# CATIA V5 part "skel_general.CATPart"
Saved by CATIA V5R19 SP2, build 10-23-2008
Part number: skel_general
Bounding box of the stored display mesh (mm): x -7 to 8, y 0 to 31.173, z 0 to 17.806
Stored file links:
  E:\TRAVAIL\IAO\skel_general.CATPart
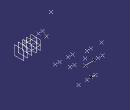
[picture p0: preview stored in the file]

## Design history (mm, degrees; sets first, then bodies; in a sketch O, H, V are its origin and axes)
Parameters
  LongueurBC = 10 mm
  LongueurBM = 10 mm
  LongueurAE = 5.4 mm
  LongueurCE = 13 mm
  LongueurDM = 16.03 mm
  LongueurDF = 6.95 mm
  LongueurCF = 18 mm
  LongueurEF = 27.8 mm
  beta = 80 deg
  LongueurAB = 10 mm
  ep = 2 mm
  Longueur_barre_4 = 20 mm
  longueur_vis = 5 mm
Body1 (main body)
  Plane1 "Plan_ref": type Offset, RefPlane yz-plane, Offset 0
  Plane2: type Offset, RefPlane Plane1, Offset 2 {= ep}
  Plane3: type Offset, RefPlane Plane1, Offset -2 {= -ep}
  Point1 "Point.F": (0, 0, 0)
  Point2 "Point.C": (0, 18 {= LongueurCF}, 0)
  Point3 "Point.E": (0, 25.7733 {= (LongueurEF *LongueurEF +LongueurCF *LongueurCF -LongueurCE *LongueurCE )/(2*LongueurCF )}, 10.4199 {= sqrt(LongueurEF *LongueurEF -(LongueurEF *LongueurEF +LongueurCF *LongueurCF -LongueurCE *LongueurCE )*(LongueurEF *LongueurEF +LongueurCF *LongueurCF -LongueurCE *LongueurCE )/(4*LongueurCF *LongueurCF ))})
  Line1 "droiteCF": type PtPt, FirstPoint Point1, SecondPoint Point2
  Line2 "Droite_creation point A": type PtDir, RefPoint Point3, Direction Line1, Start 0, End 20
  Point4 "Point.A": type OnCurve, Support Line2, Length 5.4 {= LongueurAE}
  Sketch1 "pointBintercection" on Plane1, origin (0, 0, 0), H (0, 1, 0), V (0, 0, 1)
    circle A1 centre (31.1733, 10.4199) radius 10
    point P1 (31.1733, 10.4199)
    reference projected point E1 (31.1733, 10.4199) from Point4
    circle A2 centre (18, 0) radius 10
    point P2 (18, 0)
    reference projected point E2 (18, 0) from Point2
    point P3 (27.9546, 0.9521)
    radius A1 = 10 {= LongueurAB}
    radius A2 = 10 {= LongueurBC}
    coincidence: P1 E1, P2 E2, P3 A1, P3 A2
  Sketch2 "pointBcentre" on Plane1, origin (0, 0, 0), H (0, 1, 0), V (0, 0, 1)
    circle A1 centre (27.9546, 0.9521) radius 9.2038
    point P1 (27.9546, 0.9521)
    reference projected point E1 (27.9546, 0.9521) from Sketch1.P3
    coincidence: P1 E1
  Point5 "Point.B": type Center, Curve Sketch2
  Line3 "DroiteAB": type PtPt, FirstPoint Point4, SecondPoint Point5
  Line4 "Droite.support_M": type Angle, RefPoint Point5, Curve Line3, Support Plane1, Start 0, End 20, Angle 80 {= beta}
  Point6 "Point.M": type OnCurve, Support Line4, Length 10 {= LongueurBM}
  Sketch3 "point D intercsection" on Plane1, origin (0, 0, 0), H (0, 1, 0), V (0, 0, 1)
    circle A1 centre (0, 0) radius 6.95
    circle A2 centre (19.1895, 5.7661) radius 16.03
    point P1 (19.1895, 5.7661)
    reference projected point E1 (19.1895, 5.7661) from Point6
    point P2 (3.1651, 6.1875)
    radius A2 = 16.03 {= LongueurDM}
    radius A1 = 6.95 {= LongueurDF}
    coincidence: P1 E1, P2 A2, P2 A1
  Sketch4 "point D centre" on Plane1, origin (0, 0, 0), H (0, 1, 0), V (0, 0, 1)
    circle A1 centre (3.1651, 6.1875) radius 7.2591
    point P1 (3.1651, 6.1875)
    reference projected point E1 (3.1651, 6.1875) from Sketch3.P2
    coincidence: P1 E1
  Point7 "Point.D": type Center, Curve Sketch4
  Line5 "Droite_construction_point_S": type PtPt, FirstPoint Point1, SecondPoint Point7, End 20 {= Longueur_barre_4}
  Point8 "Point.S": type OnCurve, Support Line5, Length 20 {= Longueur_barre_4}
  Line6 "Droite_construction_point_Fprim": type PtDir, RefPoint Point1, Direction Plane1, Start 0, End 2 {= ep}
  Line7 "Droite_construction_point_Cprim": type PtDir, LineFirstUpto Plane1, RefPoint Point2, Direction Line6, Start 0, End 7 {= longueur_vis+ ep}
  Line8 "Droite_construction_point_Eprim": type PtDir, RefPoint Point3, Direction Plane1, Start 0, End 7 {= ep +longueur_vis}
  Point9 "Point.Fprim": type OnCurve, Support Line6, Length 2 {= ep}
  Point10 "Point.Cprim": type OnCurve, Support Line7, Length 2 {= ep}
  Point11 "Point.Eprim": type OnCurve, Support Line8, Length 2 {= ep}
  Line9 "Droite_construction_point_Aprim": type Normal, RefPoint Point4, RefSkin Plane1, Start 0, End 2 {= ep}
  Line10 "Droite_construction_point_Bprim": type Normal, RefPoint Point5, RefSkin Plane1, Start 0, End 2 {= ep}
  Line11 "Droite_construction_point_Mprim": type Normal, RefPoint Point6, RefSkin Plane1, Start 0, End 4 {= 2*ep}
  Line12 "Droite_construction_point_Dprim": type Normal, RefPoint Point7, RefSkin Plane1, Start 0, End 6 {= 3*ep}
  Point12 "Point.Aprim": type OnCurve, Support Line9, Length 2 {= ep}
  Point13 "Point.Bprim": type OnCurve, Support Line10, Length 2 {= ep}
  Point14 "Point.Mprim": type OnCurve, Support Line11, Length 6 {= 3*ep}
  Point15 "Point.Dprim": type OnCurve, Support Line12, Length 6 {= 3*ep}
  Line13 "Droite_construction_point_Asecond": type Normal, RefPoint Point12, RefSkin Plane1, Start 0, End 4 {= 2*ep}
  Line14 "Droite_construction_point_Bsecond": type Normal, RefPoint Point13, RefSkin Plane1, Start 0, End 4 {= ep*2}
  Line15 "Droite_construction_point_Msecond": type Normal, RefPoint Point14, RefSkin Plane1, Start 0, End 4 {= 2*ep}
  Point16 "point_Asecond": type OnCurve, Support Line13, Length 4 {= 2*ep}
  Point17 "point_Bsecond": type OnCurve, Support Line14, Length 4 {= 2*ep}
  Point18 "point_Msecond": type OnCurve, Support Line15, Length 2 {= ep}
  Line16 "Droite_construction_fvis": type Normal, RefPoint Point9, RefSkin Plane3, Start 0, End 5 {= longueur_vis}
  Point19 "Point_F_vis": type OnCurve, Support Line16, Length 5 {= longueur_vis}
  Line17 "Droite_construction_Dvis": type Normal, RefPoint Point7, RefSkin Plane3, Start 0, End 2 {= ep}
  Point20 "Point_D_vis": type OnCurve, Support Line17, Length 2 {= ep}
  Point21 "Point_M_vis": type OnCurve, Support Line11, Length 2 {= ep}
  Point22 "Point_E_vis": type OnCurve, Support Line8, Length 7 {= ep+longueur_vis}
  Point23 "Point_C_vis": type OnCurve, Support Line7, Length 7 {= ep+longueur_vis}
  Line18 "Droite_construction_Avis": type Normal, RefPoint Point4, RefSkin Plane3, Start 0, End 2 {= ep}
  Point24 "Point_A_vis": type OnCurve, Support Line18, Length 2 {= ep}
  Line19 "Droite_construction_Bvis": type Normal, RefPoint Point5, RefSkin Plane3, Start 0, End 2 {= ep}
  Point25 "Point_B_vis": type OnCurve, Support Line19, Length 2 {= ep}
  Plane4: type Offset, RefPlane yz-plane, Offset 4 {= 2*ep}
  Plane5: type Offset, RefPlane yz-plane, Offset 6 {= 3*ep}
